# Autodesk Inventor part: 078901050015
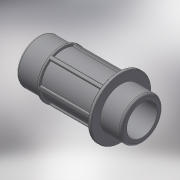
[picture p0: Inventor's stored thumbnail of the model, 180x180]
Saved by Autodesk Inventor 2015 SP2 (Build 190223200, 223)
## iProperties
Created: 2018-02
Part Number: 078901050015
Material: Generic
Description: PLASSON THREADED MALE ADAPTOR 50-1.1/2"
Document SubType Name: Modeling
Designer: KIM
Density: 1 g/cm^3
Appearance: Default
Author: KIM
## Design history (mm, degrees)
derived "078901.ipt"
feature "Solid1::078901.ipt"
tag "TaggingFeature1"
body "Solid1"
other parameters: "d4" = 2.39015, "d14" = 3.82424, "d15" = 1.91212, "d17" = 0, "d20" = 360 deg, "d40" = 24, "d41" = 47.803, "d45" = 52.5833, "d46" = 33.4621, "d47" = 2.4, "d77" = 104, "d85" = 0.47803, "d91" = 20.8, "d103" = 23.92, "d104" = 69, "d105" = 0.47803, "R_" = 47.803, "E_" = 69, "l_2" = 24, "l_" = 104
